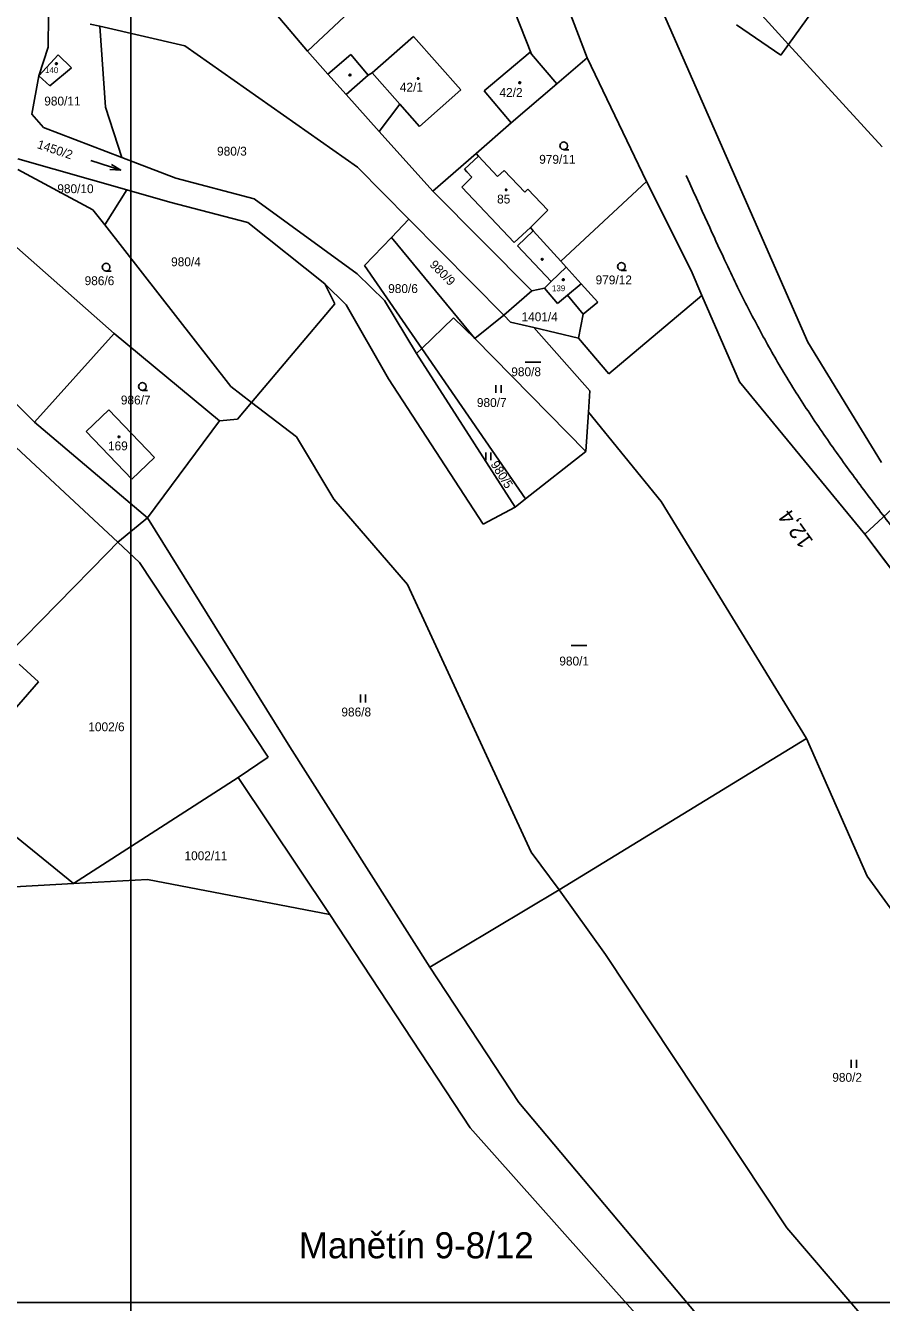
# Model space of a CAD drawing. Extents: x -852001 to -842497, y -1063614 to -1052182.
# Drawn here: x -849163.1 to -848999.2, y -1056500 to -1056255.4 of the extents above; entities that cross this region are included whole.
import ezdxf

# ---------------------------------------------------------------- set-up
doc = ezdxf.new("R2010")
doc.units = 0
for name, color, linetype in [('Default', 7, 'Continuous'), ('KLADY_ZMVM', 7, 'Continuous'), ('KN_HRANICE', 7, 'Continuous'), ('KN_KULTURY', 7, 'Continuous'), ('KN_PARCELY', 7, 'Continuous'), ('KN_SLUCKY', 7, 'Continuous'), ('LEGENDA', 7, 'Continuous'), ('obvod_stavby', 7, 'Continuous'), ('Vrstva 7', 7, 'Continuous'), ('Železniční svršek', 7, 'Continuous')]:
    doc.layers.add(name, color=color, linetype=linetype)

# ---------------------------------------------------------------- blocks, each defined once
blk = doc.blocks.new('304')
at = {"layer": 'Default'}
blk.add_lwpolyline([(0, 0), (-0.38, 0.1), (-0.65, 0.37), (-0.75, 0.74), (-0.65, 1.11), (-0.38, 1.38), (-0.01, 1.48), (0.36, 1.38), (0.63, 1.11), (0.73, 0.73), (0.63, 0.35), (0.36, 0.08), (-0.02, -0.02), (0.98, -0.02)], dxfattribs=at)
blk = doc.blocks.new('306')
at = {"layer": 'Default'}
for p, q in [((-0.5, 1.5), (-0.5, 0)), ((0.5, 0), (0.5, 1.5))]:
    blk.add_line(p, q, dxfattribs=at)
blk = doc.blocks.new('802')
at = {"layer": 'Default'}
blk.add_line((-3, 0), (3, 0), dxfattribs=at)
blk.add_lwpolyline([(1, 0.5), (3, 0), (1, -0.5)], dxfattribs=at)
blk = doc.blocks.new('804')
at = {"layer": 'Default'}
blk.add_line((-1.5, 0), (1.5, 0), dxfattribs=at)
blk = doc.blocks.new('402')
at = {"layer": 'Default'}
blk.add_lwpolyline([(0.09, 0.15), (0.18, 0), (0.09, -0.15), (-0.09, -0.15), (-0.18, 0), (-0.09, 0.15), (0.09, 0.15)], dxfattribs=at)

msp = doc.modelspace()

# ---------------------------------------------------------------- linework, layer by layer
at = {"layer": 'KLADY_ZMVM'}
msp.add_lwpolyline([(-849375, -1056500), (-848750, -1056500), (-848750, -1056000)], dxfattribs=at)
at = {"layer": 'KN_HRANICE'}
for p, q in [((-849051.11, -1056229.98), (-849034.65, -1056267.35)), ((-849016.97, -1056259.04), (-848998.88, -1056233.84)), ((-849063.18, -1056241.7), (-849055.56, -1056261.61)), ((-849123.4, -1056243.38), (-849109.14, -1056260.33)), ((-849029.32, -1056245.51), (-849016.97, -1056259.04)), ((-849071.44, -1056247.58), (-849066.2, -1056260.88)), ((-849109.14, -1056260.33), (-849097.09, -1056249.01)), ((-849158.79, -1056259.59), (-849158.72, -1056253.46)), ((-849150.75, -1056255.14), (-849148.92, -1056255.56)), ((-849018.45, -1056261.11), (-849026.95, -1056255.29)), ((-849148.92, -1056255.56), (-849132.64, -1056259.34)), ((-849148.92, -1056255.56), (-849147.84, -1056271.04)), ((-849088.84, -1056257.51), (-849096.74, -1056264.5)), ((-849088.84, -1056257.51), (-849079.77, -1056267.77)), ((-849160.55, -1056265.07), (-849158.79, -1056259.59)), ((-849132.64, -1056259.34), (-849099.56, -1056282.53)), ((-849018.45, -1056261.11), (-849016.97, -1056259.04)), ((-849016.97, -1056259.04), (-848999.06, -1056278.65)), ((-849156.88, -1056261.06), (-849160.55, -1056265.07)), ((-849154.35, -1056263.5), (-849156.88, -1056261.06)), ((-849105.2, -1056264.76), (-849109.14, -1056260.33)), ((-849105.2, -1056264.76), (-849100.84, -1056260.97)), ((-849097.53, -1056264.92), (-849100.84, -1056260.97)), ((-849066.49, -1056260.54), (-849075.28, -1056267.94)), ((-849066.2, -1056260.88), (-849066.49, -1056260.54)), ((-849061.38, -1056266.6), (-849066.2, -1056260.88)), ((-849061.38, -1056266.6), (-849055.56, -1056261.61)), ((-849044.22, -1056285.28), (-849055.56, -1056261.61)), ((-849161.91, -1056272.4), (-849160.55, -1056265.07)), ((-849160.55, -1056265.07), (-849158.48, -1056266.96)), ((-849158.48, -1056266.96), (-849154.35, -1056263.5)), ((-849101.7, -1056268.66), (-849105.2, -1056264.76)), ((-849097.53, -1056264.92), (-849096.74, -1056264.5)), ((-849070.1, -1056274.09), (-849061.38, -1056266.6)), ((-849034.65, -1056267.35), (-849013.3, -1056316.04)), ((-849095.37, -1056275.7), (-849101.7, -1056268.66)), ((-849079.77, -1056267.77), (-849087.67, -1056274.76)), ((-849070.1, -1056274.09), (-849075.28, -1056267.94)), ((-849159.69, -1056274.96), (-849161.91, -1056272.4)), ((-849147.84, -1056271.04), (-849144.65, -1056280.72)), ((-849095.37, -1056275.7), (-849091.44, -1056270.5)), ((-849087.67, -1056274.76), (-849091.44, -1056270.5)), ((-849144.65, -1056280.72), (-849159.69, -1056274.96)), ((-849070.1, -1056274.09), (-849076.82, -1056279.93)), ((-849085.1, -1056287.14), (-849095.37, -1056275.7)), ((-849164.6, -1056280.95), (-849143.72, -1056286.9)), ((-849134.31, -1056284.69), (-849144.65, -1056280.72)), ((-849076.82, -1056279.93), (-849085.1, -1056287.14)), ((-849076.82, -1056279.93), (-849076.38, -1056280.44)), ((-849076.38, -1056280.44), (-849072.72, -1056284.35)), ((-849150.22, -1056290.7), (-849164.59, -1056283.02)), ((-849119.35, -1056288.63), (-849134.31, -1056284.69)), ((-849099.56, -1056282.53), (-849089.69, -1056292.52)), ((-849072.72, -1056284.35), (-849071.45, -1056283.16)), ((-849071.45, -1056283.16), (-849067.51, -1056287.35)), ((-849147.96, -1056293.59), (-849143.72, -1056286.9)), ((-849143.72, -1056286.9), (-849135.51, -1056289.24)), ((-849085.1, -1056287.14), (-849066.14, -1056306.21)), ((-849067.51, -1056287.35), (-849066.89, -1056286.77)), ((-849066.89, -1056286.77), (-849063.1, -1056290.8)), ((-849060.61, -1056300.57), (-849044.22, -1056285.28)), ((-849035.65, -1056302.35), (-849044.22, -1056285.28)), ((-849174.78, -1056289.12), (-849146.16, -1056314.38)), ((-849135.51, -1056289.24), (-849120.55, -1056293.17)), ((-849119.35, -1056288.63), (-849099.62, -1056302.96)), ((-849161.41, -1056331.37), (-849201.97, -1056291.61)), ((-849147.96, -1056293.59), (-849150.22, -1056290.7)), ((-849063.1, -1056290.8), (-849066.44, -1056294.11)), ((-849123.81, -1056324.58), (-849147.96, -1056293.59)), ((-849120.55, -1056293.17), (-849105.79, -1056304.92)), ((-849093.06, -1056296.02), (-849089.69, -1056292.52)), ((-849089.69, -1056292.52), (-849071.52, -1056310.9)), ((-849065.87, -1056294.74), (-849066.44, -1056294.11)), ((-849098.21, -1056301.36), (-849093.06, -1056296.02)), ((-849093.06, -1056296.02), (-849077.08, -1056315.37)), ((-849060.61, -1056300.57), (-849065.87, -1056294.74)), ((-849087.23, -1056317.3), (-849098.21, -1056301.36)), ((-849062.46, -1056304.42), (-849059.57, -1056301.72)), ((-849059.57, -1056301.72), (-849060.61, -1056300.57)), ((-849056.7, -1056304.89), (-849059.57, -1056301.72)), ((-849099.62, -1056302.96), (-849094.39, -1056308.08)), ((-849033.57, -1056307.12), (-849035.65, -1056302.35)), ((-849103.9, -1056308.71), (-849105.79, -1056304.92)), ((-849105.79, -1056304.92), (-849101.71, -1056308.92)), ((-849066.14, -1056306.21), (-849071.52, -1056310.9)), ((-849066.14, -1056306.21), (-849063.74, -1056305.76)), ((-849063.74, -1056305.76), (-849062.46, -1056304.42)), ((-849063.74, -1056305.76), (-849061.22, -1056308.64)), ((-849053.54, -1056308.4), (-849056.7, -1056304.89)), ((-849119.84, -1056327.63), (-849103.9, -1056308.71)), ((-849101.71, -1056308.92), (-849093.63, -1056323.1)), ((-849094.39, -1056308.08), (-849088.27, -1056318.26)), ((-849061.22, -1056308.64), (-849059.32, -1056307.07)), ((-849059.32, -1056307.07), (-849056.31, -1056310.7)), ((-849056.31, -1056310.7), (-849053.54, -1056308.4)), ((-849051.42, -1056322.16), (-849033.57, -1056307.12)), ((-849026.35, -1056323.66), (-849033.57, -1056307.12)), ((-849081.17, -1056311.38), (-849087.23, -1056317.3)), ((-849077.08, -1056315.37), (-849081.17, -1056311.38)), ((-849077.08, -1056315.37), (-849071.52, -1056310.9)), ((-849071.52, -1056310.9), (-849070.27, -1056312.21)), ((-849056.31, -1056310.7), (-849057.24, -1056315.32)), ((-849065.77, -1056313.28), (-849070.27, -1056312.21)), ((-849057.24, -1056315.32), (-849065.77, -1056313.28)), ((-849065.77, -1056313.28), (-849055.03, -1056325.42)), ((-849161.41, -1056331.37), (-849146.16, -1056314.38)), ((-849146.16, -1056314.38), (-849125.99, -1056331.15)), ((-849077.08, -1056315.37), (-849055.79, -1056337.03)), ((-849057.24, -1056315.32), (-849051.42, -1056322.16)), ((-849013.3, -1056316.04), (-848999.16, -1056339.1)), ((-849088.27, -1056318.26), (-849087.23, -1056317.3)), ((-849069.32, -1056347.66), (-849088.27, -1056318.26)), ((-849067.39, -1056346.09), (-849087.23, -1056317.3)), ((-849181.26, -1056321.09), (-849145.42, -1056354.4)), ((-849093.63, -1056323.1), (-849075.46, -1056350.96)), ((-849002.37, -1056352.82), (-849026.35, -1056323.66)), ((-849123.81, -1056324.58), (-849119.84, -1056327.63)), ((-849055.3, -1056329.49), (-849055.03, -1056325.42)), ((-849122.51, -1056330.8), (-849119.84, -1056327.63)), ((-849119.84, -1056327.63), (-849111.2, -1056334.22)), ((-849151.51, -1056333.16), (-849147.19, -1056329.03)), ((-849147.19, -1056329.03), (-849138.43, -1056338.18)), ((-849139.79, -1056349.71), (-849125.99, -1056331.15)), ((-849125.99, -1056331.15), (-849122.51, -1056330.8)), ((-849055.79, -1056337.03), (-849055.3, -1056329.49)), ((-849041.37, -1056346.6), (-849055.3, -1056329.49)), ((-849139.79, -1056349.71), (-849161.41, -1056331.37)), ((-849142.75, -1056342.31), (-849151.51, -1056333.16)), ((-849104.06, -1056346.16), (-849111.2, -1056334.22)), ((-849138.43, -1056338.18), (-849142.75, -1056342.31)), ((-849067.39, -1056346.09), (-849055.79, -1056337.03)), ((-849089.97, -1056362.5), (-849104.06, -1056346.16)), ((-849075.46, -1056350.96), (-849069.32, -1056347.66)), ((-849069.32, -1056347.66), (-849067.39, -1056346.09)), ((-849013.53, -1056391.99), (-849041.37, -1056346.6)), ((-849145.42, -1056354.4), (-849139.79, -1056349.71)), ((-849112.51, -1056393.58), (-849139.79, -1056349.71)), ((-848986.01, -1056374.55), (-849002.37, -1056352.82)), ((-849145.42, -1056354.4), (-849147.47, -1056356.49)), ((-849145.42, -1056354.4), (-849141.27, -1056358.26)), ((-849147.47, -1056356.49), (-849166.49, -1056375.89)), ((-849116.66, -1056395.53), (-849141.27, -1056358.26)), ((-849089.97, -1056362.5), (-849066.26, -1056413.75)), ((-849160.67, -1056381.14), (-849164.34, -1056377.76)), ((-849177.57, -1056400.57), (-849160.67, -1056381.14)), ((-849060.94, -1056420.96), (-849013.53, -1056391.99)), ((-849013.53, -1056391.99), (-849001.93, -1056418.36)), ((-849085.71, -1056435.76), (-849112.51, -1056393.58)), ((-849122.42, -1056399.43), (-849116.66, -1056395.53)), ((-849153.92, -1056419.76), (-849122.42, -1056399.43)), ((-849104.83, -1056425.71), (-849122.42, -1056399.43)), ((-849177.57, -1056400.57), (-849153.92, -1056419.76)), ((-849066.26, -1056413.75), (-849060.94, -1056420.96)), ((-849153.92, -1056419.76), (-849139.78, -1056418.98)), ((-849139.78, -1056418.98), (-849104.83, -1056425.71)), ((-849001.93, -1056418.36), (-848977.76, -1056451.81)), ((-849153.92, -1056419.76), (-849174.42, -1056420.91)), ((-849085.71, -1056435.76), (-849060.94, -1056420.96)), ((-849052.06, -1056433.36), (-849060.94, -1056420.96)), ((-849104.83, -1056425.71), (-849077.96, -1056466.55)), ((-849017.3, -1056485.72), (-849052.06, -1056433.36)), ((-849068.63, -1056461.72), (-849085.71, -1056435.76)), ((-849017.61, -1056522.4), (-849068.63, -1056461.72)), ((-849077.96, -1056466.55), (-849036.41, -1056513.21)), ((-848985.11, -1056523.29), (-849017.3, -1056485.72))]:
    msp.add_line(p, q, dxfattribs=at)
at = {"layer": 'KN_SLUCKY'}
for p, q in [((-849097.53, -1056264.92), (-849101.7, -1056268.66)), ((-849091.44, -1056270.5), (-849096.74, -1056264.5)), ((-849079.06, -1056282.95), (-849076.38, -1056280.44)), ((-849079.55, -1056286.37), (-849077.65, -1056284.44)), ((-849078.61, -1056283.42), (-849079.06, -1056282.95)), ((-849077.65, -1056284.44), (-849078.61, -1056283.42)), ((-849069.52, -1056297.01), (-849079.55, -1056286.37)), ((-849066.44, -1056294.11), (-849069.52, -1056297.01)), ((-849068.9, -1056297.62), (-849065.87, -1056294.74)), ((-849062.46, -1056304.42), (-849068.9, -1056297.62)), ((-849059.32, -1056307.07), (-849056.7, -1056304.89))]:
    msp.add_line(p, q, dxfattribs=at)
at = {"layer": 'LEGENDA'}
msp.add_lwpolyline([(-849142.95, -1056625.24), (-848548.95, -1056625.24), (-848548.95, -1056205.24), (-849142.95, -1056205.24)], close=True, dxfattribs=at)
at = {"layer": 'obvod_stavby'}
msp.add_lwpolyline([(-848936.28, -1056450.22), (-848946.06, -1056425.85), (-848960.15, -1056409.91), (-848986.01, -1056374.55), (-849002.37, -1056352.82), (-848990.06, -1056341.42)], dxfattribs=at)
at = {"layer": 'Železniční svršek'}
msp.add_open_spline([(-848892.81, -1056486.91), (-848898.96, -1056478.95), (-848904.39, -1056471.91), (-848910.36, -1056464.18), (-848915.68, -1056457.29), (-848922.02, -1056449.05), (-848928.2, -1056441.01), (-848934.22, -1056433.18), (-848940.17, -1056425.45), (-848946.67, -1056417), (-848952.25, -1056409.77), (-848955.57, -1056405.45), (-848960.77, -1056398.71), (-848966.2, -1056391.67), (-848971.61, -1056384.64), (-848977.18, -1056377.42), (-848982.34, -1056370.71), (-848987.69, -1056363.77), (-848993.84, -1056355.79), (-848999.77, -1056348.09), (-849005.4, -1056340.62), (-849010.95, -1056332.79), (-849016.27, -1056324.7), (-849020.78, -1056317.03), (-849025.01, -1056309.08), (-849028.91, -1056301.1), (-849032.78, -1056292.63), (-849036.57, -1056284.16)], degree=3, dxfattribs=at)

# ---------------------------------------------------------------- block references
at = {"layer": 'KN_KULTURY'}
for name, p in [('402', (-849157.21, -1056262.73)), ('402', (-849101, -1056264.89)), ('402', (-849087.92, -1056265.56)), ('402', (-849068.46, -1056266.38)), ('304', (-849060.04, -1056279.2)), ('402', (-849071.07, -1056286.9)), ('304', (-849147.68, -1056302.45)), ('402', (-849064.17, -1056300.21)), ('304', (-849049, -1056302.3)), ('402', (-849060.14, -1056304.1)), ('804', (-849065.96, -1056319.89)), ('304', (-849140.74, -1056325.3)), ('306', (-849072.55, -1056325.79)), ('402', (-849145.24, -1056334.2)), ('306', (-849074.49, -1056338.69)), ('804', (-849057.13, -1056374.15)), ('306', (-849098.5, -1056385.06)), ('306', (-849004.48, -1056455.04))]:
    msp.add_blockref(name, p, dxfattribs=at)
at = {"layer": 'KN_KULTURY', "rotation": -17.944195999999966}
msp.add_blockref('802', (-849147.75, -1056282.2), dxfattribs=at)

# ---------------------------------------------------------------- texts
at = {"layer": 'KLADY_ZMVM'}
msp.add_text('Manětín 9-8/12', height=5, dxfattribs=at).set_placement((-849110.77, -1056491.55))
at = {"layer": 'KN_PARCELY'}
for s, height, p in [('140', 1.14, (-849159.4, -1056264.54)), ('42/1', 1.7, (-849091.43, -1056268.07)), ('42/2', 1.7, (-849072.35, -1056269.09)), ('980/11', 1.7, (-849159.54, -1056270.74)), ('980/3', 1.7, (-849126.44, -1056280.34)), ('979/11', 1.7, (-849064.74, -1056281.9)), ('980/10', 1.7, (-849157.04, -1056287.53)), ('85', 1.7, (-849072.81, -1056289.51)), ('980/4', 1.7, (-849135.24, -1056301.53)), ('986/6', 1.7, (-849151.81, -1056305.15)), ('979/12', 1.7, (-849053.94, -1056305)), ('980/6', 1.7, (-849093.67, -1056306.66)), ('139', 1.14, (-849062.3, -1056306.31)), ('1401/4', 1.7, (-849068.13, -1056312.06)), ('980/8', 1.7, (-849070.09, -1056322.59)), ('986/7', 1.7, (-849144.87, -1056328)), ('980/7', 1.7, (-849076.68, -1056328.49)), ('169', 1.7, (-849147.34, -1056336.79)), ('980/1', 1.7, (-849060.89, -1056378)), ('986/8', 1.7, (-849102.63, -1056387.76)), ('1002/6', 1.7, (-849151.1, -1056390.59)), ('1002/11', 1.7, (-849132.68, -1056415.29)), ('980/2', 1.7, (-849008.61, -1056457.74))]:
    msp.add_text(s, height=height, dxfattribs=at).set_placement(p)
for s, rotation, p in [('1450/2', 341.54, (-849161.04, -1056278.88)), ('980/9', 314.783, (-849085.85, -1056301.37)), ('980/5', 302.121, (-849074.12, -1056339.47))]:
    msp.add_text(s, height=1.7, rotation=rotation, dxfattribs=at).set_placement(p)
at = {"layer": 'Vrstva 7'}
msp.add_text('12,4', height=3, rotation=125.7923, dxfattribs=at).set_placement((-849012.14, -1056354.16))

doc.saveas('drawing.dxf')
